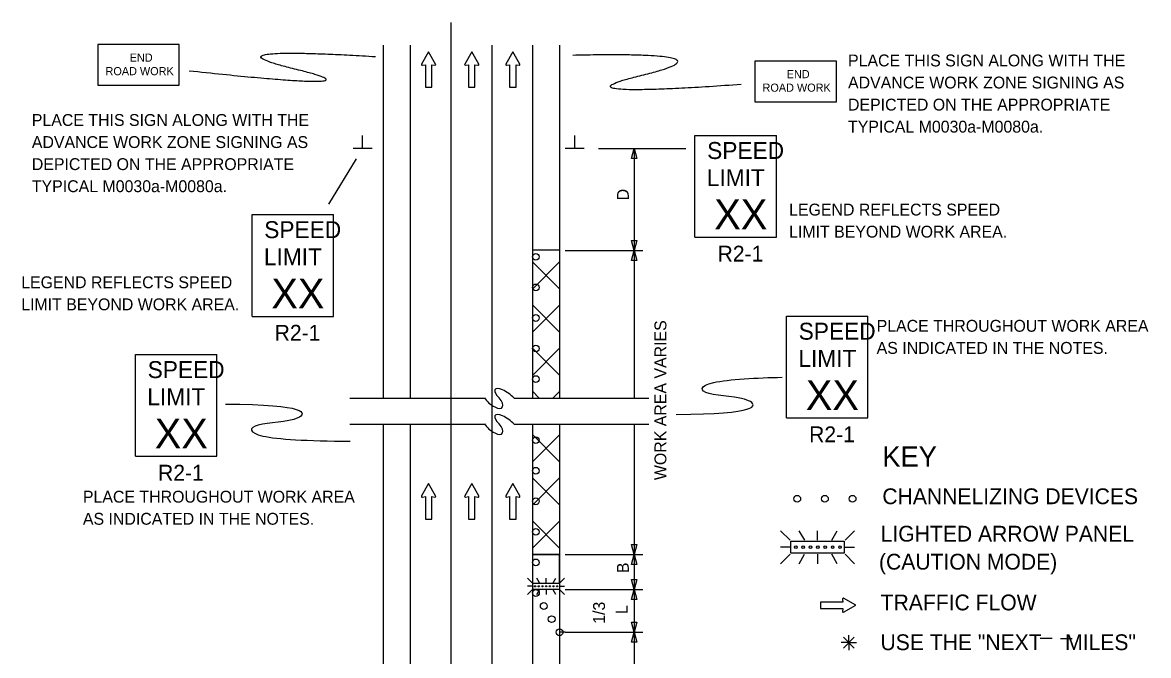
# Model space of a CAD drawing. Extents: x 16733 to 18471, y 7027 to 8225.
# Drawn here: x 16733 to 17397, y 7852 to 8225 of the extents above; entities that cross this region are included whole.
import ezdxf

# ---------------------------------------------------------------- set-up
doc = ezdxf.new("R2010")
doc.units = 0
for name, color, linetype in [('ALI_LEGAL_EX', 7, 'Continuous'), ('MT_SCRATCH_LEVEL_A', 7, 'Continuous'), ('MT_SCRATCH_LEVEL_E', 7, 'Continuous'), ('PAVT_EDGE_EX', 7, 'Continuous'), ('TRAFFIC_SIGNS_PR', 7, 'Continuous'), ('TYPICAL_EX', 7, 'Continuous'), ('TYPICAL_TEXT_DIMEN_EX', 7, 'Continuous'), ('TYPICAL_TEXT_DIMEN_PR', 7, 'Continuous')]:
    doc.layers.add(name, color=color, linetype=linetype)

msp = doc.modelspace()

# ---------------------------------------------------------------- linework, layer by layer
at = {"layer": 'ALI_LEGAL_EX'}
for points in [[(16985.65, 8225.29), (16985.65, 8200.29)], [(16985.65, 8216), (16985.65, 8191)], [(16985.65, 8211.96), (16985.65, 8200.29)], [(17009.65, 8211.96), (17009.65, 8200.29)], [(16985.65, 8125.29), (16985.65, 8100.29)], [(16985.65, 8125.29), (16985.65, 8100.29)], [(17009.65, 8125.29), (17009.65, 8100.29)], [(16985.65, 8025.29), (16985.65, 8004.01)], [(17009.65, 8025.29), (17009.65, 8000.29)], [(16985.65, 7961.57), (16985.65, 7936.57)], [(16985.65, 7925.29), (16985.65, 7900.29)], [(17009.65, 7925.29), (17009.65, 7900.29)]]:
    msp.add_lwpolyline(points, dxfattribs=at)
at = {"layer": 'MT_SCRATCH_LEVEL_A'}
for p, q in [((17049.65, 8068.41), (17033.65, 8084.41)), ((17033.65, 8068.3), (17049.65, 8084.3)), ((17049.65, 8042.96), (17033.65, 8058.96)), ((17033.65, 8042.85), (17049.65, 8058.85)), ((17049.65, 8017.5), (17033.65, 8033.5)), ((17033.65, 8017.39), (17049.65, 8033.39)), ((17037.68, 8004.02), (17033.65, 8008.05)), ((17045.64, 8003.92), (17049.65, 8007.94)), ((17049.65, 7966.59), (17033.65, 7982.59)), ((17033.65, 7966.48), (17049.65, 7982.48)), ((17049.65, 7941.13), (17033.65, 7957.13)), ((17033.65, 7941.02), (17049.65, 7957.02)), ((17049.65, 7915.68), (17033.65, 7931.68)), ((17033.65, 7915.57), (17049.65, 7931.57))]:
    msp.add_line(p, q, dxfattribs=at)
at = {"layer": 'MT_SCRATCH_LEVEL_E'}
for p, q in [((16972.46, 8208.07), (16968.34, 8200.83)), ((16972.46, 8208.07), (16968.34, 8200.83)), ((16976.6, 8200.83), (16972.46, 8208.07)), ((16976.6, 8200.83), (16972.46, 8208.07)), ((16997.88, 8208.07), (16993.77, 8200.83)), ((16997.88, 8208.07), (16993.77, 8200.83)), ((17002.03, 8200.83), (16997.88, 8208.07)), ((17002.03, 8200.83), (16997.88, 8208.07)), ((17022.09, 8208.07), (17017.98, 8200.83)), ((17022.09, 8208.07), (17017.98, 8200.83)), ((17026.24, 8200.83), (17022.09, 8208.07)), ((17026.24, 8200.83), (17022.09, 8208.07)), ((16968.83, 8200.14), (16970.6, 8200.46)), ((16968.83, 8200.14), (16970.6, 8200.46)), ((16970.6, 8200.46), (16970.6, 8187.2)), ((16970.6, 8200.46), (16970.6, 8187.2)), ((16974.35, 8187.2), (16974.35, 8200.46)), ((16974.35, 8200.46), (16976.12, 8200.14)), ((16974.35, 8187.2), (16974.35, 8200.46)), ((16974.35, 8200.46), (16976.12, 8200.14)), ((16994.25, 8200.14), (16996.03, 8200.46)), ((16994.25, 8200.14), (16996.03, 8200.46)), ((16996.03, 8200.46), (16996.03, 8187.2)), ((16996.03, 8200.46), (16996.03, 8187.2)), ((16999.77, 8187.2), (16999.77, 8200.46)), ((16999.77, 8200.46), (17001.55, 8200.14)), ((16999.77, 8187.2), (16999.77, 8200.46)), ((16999.77, 8200.46), (17001.55, 8200.14)), ((17018.47, 8200.14), (17020.24, 8200.46)), ((17018.47, 8200.14), (17020.24, 8200.46)), ((17020.24, 8200.46), (17020.24, 8187.2)), ((17020.24, 8200.46), (17020.24, 8187.2)), ((17023.98, 8187.2), (17023.98, 8200.46)), ((17023.98, 8200.46), (17025.76, 8200.14)), ((17023.98, 8187.2), (17023.98, 8200.46)), ((17023.98, 8200.46), (17025.76, 8200.14)), ((16970.6, 8187.2), (16974.35, 8187.2)), ((16970.6, 8187.2), (16974.35, 8187.2)), ((16996.03, 8187.2), (16999.77, 8187.2)), ((16996.03, 8187.2), (16999.77, 8187.2)), ((17020.24, 8187.2), (17023.98, 8187.2)), ((17020.24, 8187.2), (17023.98, 8187.2)), ((16972.46, 7953.64), (16968.34, 7946.4)), ((16972.46, 7953.64), (16968.34, 7946.4)), ((16976.6, 7946.4), (16972.46, 7953.64)), ((16976.6, 7946.4), (16972.46, 7953.64)), ((16997.88, 7953.64), (16993.77, 7946.4)), ((16997.88, 7953.64), (16993.77, 7946.4)), ((17002.03, 7946.4), (16997.88, 7953.64)), ((17002.03, 7946.4), (16997.88, 7953.64)), ((17022.09, 7953.64), (17017.98, 7946.4)), ((17022.09, 7953.64), (17017.98, 7946.4)), ((17026.24, 7946.4), (17022.09, 7953.64)), ((17026.24, 7946.4), (17022.09, 7953.64)), ((16968.83, 7945.72), (16970.6, 7946.03)), ((16968.83, 7945.72), (16970.6, 7946.03)), ((16970.6, 7946.03), (16970.6, 7932.78)), ((16970.6, 7946.03), (16970.6, 7932.78)), ((16974.35, 7932.78), (16974.35, 7946.03)), ((16974.35, 7946.03), (16976.12, 7945.72)), ((16974.35, 7932.78), (16974.35, 7946.03)), ((16974.35, 7946.03), (16976.12, 7945.72)), ((16994.25, 7945.72), (16996.03, 7946.03)), ((16994.25, 7945.72), (16996.03, 7946.03)), ((16996.03, 7946.03), (16996.03, 7932.78)), ((16996.03, 7946.03), (16996.03, 7932.78)), ((16999.77, 7932.78), (16999.77, 7946.03)), ((16999.77, 7946.03), (17001.55, 7945.72)), ((16999.77, 7932.78), (16999.77, 7946.03)), ((16999.77, 7946.03), (17001.55, 7945.72)), ((17018.47, 7945.72), (17020.24, 7946.03)), ((17018.47, 7945.72), (17020.24, 7946.03)), ((17020.24, 7946.03), (17020.24, 7932.78)), ((17020.24, 7946.03), (17020.24, 7932.78)), ((17023.98, 7932.78), (17023.98, 7946.03)), ((17023.98, 7946.03), (17025.76, 7945.72)), ((17023.98, 7932.78), (17023.98, 7946.03)), ((17023.98, 7946.03), (17025.76, 7945.72)), ((16970.6, 7932.78), (16974.35, 7932.78)), ((16970.6, 7932.78), (16974.35, 7932.78)), ((16996.03, 7932.78), (16999.77, 7932.78)), ((16996.03, 7932.78), (16999.77, 7932.78)), ((17020.24, 7932.78), (17023.98, 7932.78)), ((17020.24, 7932.78), (17023.98, 7932.78)), ((17216.64, 7883.85), (17203.38, 7883.85)), ((17203.38, 7883.85), (17203.38, 7880.11)), ((17216.64, 7883.85), (17203.38, 7883.85)), ((17203.38, 7883.85), (17203.38, 7880.11)), ((17216.33, 7885.63), (17216.64, 7883.85)), ((17216.33, 7885.63), (17216.64, 7883.85)), ((17224.25, 7882), (17217.01, 7886.11)), ((17224.25, 7882), (17217.01, 7886.11)), ((17217.01, 7877.85), (17224.25, 7882)), ((17217.01, 7877.85), (17224.25, 7882)), ((17203.38, 7880.11), (17216.64, 7880.11)), ((17203.38, 7880.11), (17216.64, 7880.11)), ((17216.64, 7880.11), (17216.33, 7878.33)), ((17216.64, 7880.11), (17216.33, 7878.33))]:
    msp.add_line(p, q, dxfattribs=at)
for centre, start, end in [((16968.75, 8200.6), 150.42484, 279.96381), ((16968.75, 8200.6), 150.42484, 279.96381), ((16976.19, 8200.6), 260.03619, 29.77312), ((16976.19, 8200.6), 260.03619, 29.77312), ((16994.18, 8200.6), 150.42484, 279.96381), ((16994.18, 8200.6), 150.42484, 279.96381), ((17001.62, 8200.6), 260.03619, 29.77312), ((17001.62, 8200.6), 260.03619, 29.77312), ((17018.39, 8200.6), 150.42484, 279.96381), ((17018.39, 8200.6), 150.42484, 279.96381), ((17025.83, 8200.6), 260.03619, 29.77312), ((17025.83, 8200.6), 260.03619, 29.77312), ((16968.75, 7946.18), 150.42484, 279.96381), ((16968.75, 7946.18), 150.42484, 279.96381), ((16976.19, 7946.18), 260.03619, 29.77312), ((16976.19, 7946.18), 260.03619, 29.77312), ((16994.18, 7946.18), 150.42484, 279.96381), ((16994.18, 7946.18), 150.42484, 279.96381), ((17001.62, 7946.18), 260.03619, 29.77312), ((17001.62, 7946.18), 260.03619, 29.77312), ((17018.39, 7946.18), 150.42484, 279.96381), ((17018.39, 7946.18), 150.42484, 279.96381), ((17025.83, 7946.18), 260.03619, 29.77312), ((17025.83, 7946.18), 260.03619, 29.77312), ((17216.79, 7885.7), 60.42484, 189.96381), ((17216.79, 7885.7), 60.42484, 189.96381), ((17216.79, 7878.26), 170.03619, 299.77312), ((17216.79, 7878.26), 170.03619, 299.77312)]:
    msp.add_arc(centre, 0.463, start, end, dxfattribs=at)
at = {"layer": 'PAVT_EDGE_EX'}
for p, q in [((16945.65, 8211.96), (16945.65, 8004.01)), ((16961.65, 8211.96), (16961.65, 8004.01)), ((16985.65, 8211.96), (16985.65, 7344.79)), ((17009.65, 8211.96), (17009.65, 7344.79)), ((17033.65, 8211.96), (17033.65, 8004.01)), ((17049.65, 8211.96), (17049.65, 8004.01)), ((16985.65, 8097.28), (16985.65, 7344.79)), ((17009.65, 8097.28), (17009.65, 7344.79)), ((17033.65, 8091.4), (17049.65, 8091.4)), ((17035.65, 8015.25), (17035.65, 8015.25)), ((16945.65, 7988.69), (16945.65, 7942.5)), ((16961.65, 7988.69), (16961.65, 7942.41)), ((17033.65, 7988.69), (17033.65, 7942.16)), ((17049.65, 7988.69), (17049.65, 7942.41)), ((16945.65, 7942.5), (16945.65, 7379.34)), ((16961.65, 7942.41), (16961.65, 7379.34)), ((17033.65, 7942.16), (17033.65, 7379.34)), ((17049.65, 7942.41), (17049.65, 7379.34)), ((17033.65, 7911.96), (17049.65, 7911.96)), ((17049.65, 7911.96), (17033.65, 7911.96)), ((17033.65, 7911.96), (17033.65, 7894.97)), ((17049.65, 7894.97), (17049.65, 7911.96)), ((17033.65, 7894.97), (17049.65, 7894.97)), ((17033.65, 7894.97), (17049.65, 7894.97)), ((17052.95, 7866.13), (17049.65, 7866.13))]:
    msp.add_line(p, q, dxfattribs=at)
at = {"layer": 'TRAFFIC_SIGNS_PR'}
for p, q in [((17129.39, 8158.81), (17177.39, 8158.81)), ((17129.39, 8098.81), (17129.39, 8158.81)), ((17177.39, 8098.81), (17177.39, 8158.81)), ((16868.43, 8112.19), (16916.43, 8112.19)), ((16868.43, 8052.19), (16868.43, 8112.19)), ((16916.43, 8052.19), (16916.43, 8112.19)), ((17129.39, 8098.81), (17177.39, 8098.81)), ((16868.43, 8052.19), (16916.43, 8052.19)), ((17183.35, 8052.36), (17231.35, 8052.36)), ((17183.35, 7992.36), (17183.35, 8052.36)), ((17231.35, 7992.36), (17231.35, 8052.36)), ((16799.74, 8029.76), (16847.74, 8029.76)), ((16799.74, 7969.76), (16799.74, 8029.76)), ((16847.74, 7969.76), (16847.74, 8029.76)), ((17183.35, 7992.36), (17231.35, 7992.36)), ((16799.74, 7969.76), (16847.74, 7969.76)), ((17179.9, 7925.91), (17185.53, 7920.27)), ((17194.07, 7920.27), (17190.82, 7925.91)), ((17201.7, 7920.27), (17201.7, 7925.91)), ((17209.97, 7920.27), (17213.23, 7925.91)), ((17217.87, 7920.27), (17223.52, 7925.91)), ((17185.53, 7916.21), (17179.9, 7916.21)), ((17188.81, 7916.21), (17188.81, 7916.21)), ((17193.16, 7916.21), (17193.16, 7916.21)), ((17197.5, 7916.21), (17197.5, 7916.21)), ((17201.85, 7916.21), (17201.85, 7916.21)), ((17206.2, 7916.21), (17206.2, 7916.21)), ((17210.55, 7916.21), (17210.55, 7916.21)), ((17214.89, 7916.21), (17214.89, 7916.21)), ((17217.87, 7916.21), (17223.52, 7916.21)), ((17179.9, 7906.51), (17185.53, 7912.14)), ((17190.77, 7906.5), (17194.02, 7912.14)), ((17201.7, 7912.14), (17201.7, 7906.5)), ((17213.28, 7906.5), (17210.02, 7912.14)), ((17217.87, 7912.14), (17223.52, 7906.5)), ((17030.76, 7898.01), (17033.58, 7895.19)), ((17037.85, 7895.19), (17036.22, 7898.01)), ((17041.67, 7895.19), (17041.67, 7898.01)), ((17045.8, 7895.19), (17047.43, 7898.01)), ((17049.75, 7895.19), (17052.57, 7898.01)), ((17033.58, 7893.16), (17030.76, 7893.16)), ((17030.76, 7888.31), (17033.58, 7891.13)), ((17035.22, 7893.16), (17035.22, 7893.16)), ((17036.2, 7888.31), (17037.83, 7891.13)), ((17037.4, 7893.16), (17037.4, 7893.16)), ((17039.57, 7893.16), (17039.57, 7893.16)), ((17041.67, 7891.13), (17041.67, 7888.31)), ((17041.74, 7893.16), (17041.74, 7893.16)), ((17043.92, 7893.16), (17043.92, 7893.16)), ((17047.46, 7888.31), (17045.83, 7891.13)), ((17046.09, 7893.16), (17046.09, 7893.16)), ((17048.26, 7893.16), (17048.26, 7893.16)), ((17049.75, 7893.16), (17052.57, 7893.16)), ((17049.75, 7891.13), (17052.57, 7888.31))]:
    msp.add_line(p, q, dxfattribs=at)
for points in [[(16777.61, 8188.32), (16825.61, 8188.32), (16825.61, 8212.32), (16777.61, 8212.32)], [(17164.73, 8178.59), (17212.73, 8178.59), (17212.73, 8202.59), (17164.73, 8202.59)], [(17217.41, 7912.61), (17186, 7912.61), (17186, 7919.81), (17217.41, 7919.81)], [(17049.52, 7891.36), (17033.81, 7891.36), (17033.81, 7894.96), (17049.52, 7894.96)]]:
    msp.add_lwpolyline(points, close=True, dxfattribs=at)
for centre, radius in [((17035.65, 8087.25), 2), ((17035.65, 8069.25), 2), ((17035.65, 8051.25), 2), ((17035.65, 8033.25), 2), ((17035.65, 8015.25), 2), ((17035.65, 7979.25), 2), ((17035.65, 7961.25), 2), ((17035.65, 7943.25), 2), ((17189.7, 7944.73), 2), ((17206, 7944.73), 2), ((17222.3, 7944.73), 2), ((17035.65, 7925.25), 2), ((17188.85, 7916.21), 0.758), ((17193.16, 7916.21), 0.758), ((17197.5, 7916.21), 0.758), ((17201.85, 7916.21), 0.758), ((17206.2, 7916.21), 0.758), ((17210.55, 7916.21), 0.758), ((17214.89, 7916.21), 0.758), ((17035.65, 7907.25), 2), ((17035.65, 7889.25), 2), ((17035.7, 7889.25), 2), ((17035.24, 7893.16), 0.379), ((17037.39, 7893.16), 0.379), ((17039.57, 7893.16), 0.379), ((17041.74, 7893.16), 0.379), ((17043.91, 7893.16), 0.379), ((17046.09, 7893.16), 0.379), ((17048.26, 7893.16), 0.379), ((17040.35, 7881.55), 2), ((17044.99, 7873.84), 2), ((17049.65, 7866.13), 2)]:
    msp.add_circle(centre, radius, dxfattribs=at)
for points in [[(16831.42, 8196.9), (16950.78, 8184.01), (16836.87, 8211.59), (16941.12, 8205.24)], [(17156.66, 8188.77), (17041.44, 8180.53), (17155.34, 8208.11), (17057.4, 8205.95)]]:
    msp.add_open_spline(points, degree=2, dxfattribs=at)
at = {"layer": 'TYPICAL_EX'}
for p, q in [((16926.17, 8004.01), (17005.48, 8004.01)), ((17022.9, 8004.01), (17102.17, 8004.01)), ((16926.17, 7988.69), (17005.48, 7988.69)), ((17022.9, 7988.69), (17102.17, 7988.69))]:
    msp.add_line(p, q, dxfattribs=at)
for centre, major_axis, ratio, start_param, end_param in [((17018.27, 8004.28), (6.66, -4.85), 0.346236, 1.077134, 4.299707), ((17010.23, 8003.47), (-5.67, 4.94), 0.423114, 0.994299, 4.377734), ((17018.27, 7988.96), (6.66, -4.85), 0.346236, 1.077134, 4.299707), ((17010.23, 7988.15), (-5.67, 4.94), 0.423114, 0.994299, 4.377734)]:
    msp.add_ellipse(centre, major_axis=major_axis, ratio=ratio, start_param=start_param, end_param=end_param, dxfattribs=at)
at = {"layer": 'TYPICAL_TEXT_DIMEN_EX'}
for p, q in [((17332.79, 7862.53), (17339.79, 7862.53)), ((17344.74, 7862.38), (17351.74, 7862.38))]:
    msp.add_line(p, q, dxfattribs=at)
at = {"layer": 'TYPICAL_TEXT_DIMEN_PR'}
for p, q in [((16933.63, 8151), (16933.63, 8158.78)), ((17058.58, 8151), (17058.58, 8158.78)), ((16939.26, 8151), (16928.01, 8151)), ((17064.21, 8151), (17052.96, 8151)), ((17072.65, 8151), (17124.05, 8151)), ((17092.08, 8145.14), (17093.65, 8151)), ((17093.65, 8151), (17093.65, 8091)), ((17093.65, 8151), (17095.22, 8145.14)), ((16913.77, 8118.29), (16929.93, 8144.91)), ((17093.65, 8145.14), (17092.08, 8145.14)), ((17095.22, 8145.14), (17093.65, 8145.14)), ((17093.65, 8091), (17092.08, 8096.86)), ((17092.08, 8096.86), (17093.65, 8096.86)), ((17093.65, 8096.86), (17095.22, 8096.86)), ((17095.22, 8096.86), (17093.65, 8091)), ((17052.95, 8091), (17098.65, 8091)), ((17092.08, 8085.14), (17093.65, 8091)), ((17093.65, 8091), (17095.22, 8085.14)), ((17093.65, 8091), (17093.65, 8003.81)), ((17093.65, 8085.14), (17092.08, 8085.14)), ((17095.22, 8085.14), (17093.65, 8085.14)), ((17093.65, 7988.65), (17093.65, 7911.96)), ((17093.65, 7911.96), (17092.08, 7917.82)), ((17092.08, 7917.82), (17093.65, 7917.82)), ((17093.65, 7917.82), (17095.22, 7917.82)), ((17095.22, 7917.82), (17093.65, 7911.96)), ((17052.95, 7911.96), (17098.65, 7911.96)), ((17092.08, 7906.1), (17093.65, 7911.96)), ((17093.65, 7911.96), (17093.65, 7891.25)), ((17093.65, 7911.96), (17095.22, 7906.1)), ((17093.65, 7906.1), (17092.08, 7906.1)), ((17095.22, 7906.1), (17093.65, 7906.1)), ((17093.65, 7891.25), (17092.08, 7897.11)), ((17092.08, 7897.11), (17093.65, 7897.11)), ((17093.65, 7897.11), (17095.22, 7897.11)), ((17095.22, 7897.11), (17093.65, 7891.25)), ((17052.95, 7891.25), (17098.65, 7891.25)), ((17092.08, 7885.39), (17093.65, 7891.25)), ((17093.65, 7891.25), (17093.65, 7866.13)), ((17093.65, 7891.25), (17095.22, 7885.39)), ((17093.65, 7885.39), (17092.08, 7885.39)), ((17095.22, 7885.39), (17093.65, 7885.39)), ((17093.65, 7866.13), (17092.08, 7871.99)), ((17092.08, 7871.99), (17093.65, 7871.99)), ((17093.65, 7871.99), (17095.22, 7871.99)), ((17095.22, 7871.99), (17093.65, 7866.13)), ((17052.95, 7866.13), (17098.65, 7866.13)), ((17092.08, 7860.27), (17093.65, 7866.13)), ((17093.65, 7866.13), (17093.65, 7806.13)), ((17093.65, 7866.13), (17095.22, 7860.27)), ((17216.95, 7863.21), (17223.32, 7856.83)), ((17223.32, 7863.21), (17216.95, 7856.83)), ((17220.14, 7860.02), (17220.14, 7864.48)), ((17093.65, 7860.27), (17092.08, 7860.27)), ((17095.22, 7860.27), (17093.65, 7860.27)), ((17220.14, 7860.02), (17215.6, 7860.02)), ((17220.14, 7860.02), (17223.32, 7860.02)), ((17220.14, 7860.02), (17224.61, 7860.02)), ((17220.14, 7860.02), (17220.14, 7855.52))]:
    msp.add_line(p, q, dxfattribs=at)
for points in [[(17118.4, 7994.46), (17166.86, 7994.46), (17166.86, 8005.21), (17131.95, 8005.21), (17131.95, 8014.26), (17166.15, 8016.02), (17180.88, 8016.31)], [(16852.78, 8000.44), (16901.25, 8000.44), (16901.25, 7989.68), (16866.33, 7989.68), (16866.33, 7980.63), (16900.54, 7978.87), (16926.31, 7978.58)]]:
    msp.add_open_spline(points, degree=3, dxfattribs=at)

# ---------------------------------------------------------------- texts
at = {"layer": 'TRAFFIC_SIGNS_PR'}
for s, height, p in [('END', 4.789, (16796.36, 8202.23)), ('PLACE THIS SIGN ALONG WITH THE', 7, (17219.61, 8199.44)), ('ROAD WORK', 4.789, (16782.12, 8194.25)), ('END', 4.789, (17183.48, 8192.5)), ('ADVANCE WORK ZONE SIGNING AS', 7, (17219.61, 8186.44)), ('ROAD WORK', 4.789, (17169.24, 8184.52)), ('DEPICTED ON THE APPROPRIATE', 7, (17219.61, 8173.44)), ('PLACE THIS SIGN ALONG WITH THE', 7, (16738.72, 8164.36)), ('TYPICAL M0030a-M0080a.', 7, (17219.61, 8160.44)), ('ADVANCE WORK ZONE SIGNING AS', 7, (16738.72, 8151.36)), ('SPEED', 10, (17136.6, 8144.89)), ('DEPICTED ON THE APPROPRIATE', 7, (16738.72, 8138.36)), ('LIMIT', 10, (17136.4, 8128.89)), ('TYPICAL M0030a-M0080a.', 7, (16738.72, 8125.36)), ('XX', 17.538, (17140.78, 8103.51)), ('LEGEND REFLECTS SPEED', 7, (17184.9, 8111.59)), ('SPEED', 10, (16875.64, 8098.27)), ('LIMIT BEYOND WORK AREA.', 7, (17184.9, 8098.59)), ('R2-1', 9.3, (17142.74, 8084.51)), ('LIMIT', 10, (16875.43, 8082.27)), ('LEGEND REFLECTS SPEED', 7, (16732.45, 8068.77)), ('XX', 17.538, (16879.82, 8056.89)), ('LIMIT BEYOND WORK AREA.', 7, (16732.45, 8055.77)), ('R2-1', 9.3, (16881.77, 8037.9)), ('SPEED', 10, (17190.55, 8038.44)), ('PLACE THROUGHOUT WORK AREA', 7, (17236.47, 8043.12)), ('AS INDICATED IN THE NOTES.', 7, (17236.47, 8030.12)), ('LIMIT', 10, (17190.35, 8022.44)), ('SPEED', 10, (16806.95, 8015.83)), ('XX', 17.538, (17194.74, 7997.06)), ('LIMIT', 10, (16806.74, 7999.83)), ('XX', 17.538, (16811.13, 7974.45)), ('R2-1', 9.3, (17196.69, 7978.06)), ('R2-1', 9.3, (16813.08, 7955.46)), ('PLACE THROUGHOUT WORK AREA', 7, (16768.81, 7942.45)), ('AS INDICATED IN THE NOTES.', 7, (16768.81, 7929.45))]:
    msp.add_text(s, height=height, dxfattribs=at).set_placement(p)
at = {"layer": 'TYPICAL_TEXT_DIMEN_EX'}
for s, height, p in [('KEY', 12, (17239.84, 7963.61)), ('CHANNELIZING DEVICES', 9.3, (17239.84, 7941.56)), ('LIGHTED ARROW PANEL', 9.3, (17238.84, 7919.51)), ('(CAUTION MODE)', 9.3, (17237.85, 7903.01)), ('TRAFFIC FLOW', 9.3, (17238.84, 7879.01)), ('USE THE "NEXT    MILES"', 9.3, (17238.75, 7855.57))]:
    msp.add_text(s, height=height, dxfattribs=at).set_placement(p)
at = {"layer": 'TYPICAL_TEXT_DIMEN_PR'}
for s, p in [('D', (17090.46, 8120.54)), ('WORK AREA VARIES', (17112.58, 7955.74)), ('B', (17090.46, 7900.95)), ('1/3', (17076.41, 7871.08)), ('L', (17089.71, 7876.87))]:
    msp.add_text(s, height=7, rotation=90, dxfattribs=at).set_placement(p)

doc.saveas('drawing.dxf')
